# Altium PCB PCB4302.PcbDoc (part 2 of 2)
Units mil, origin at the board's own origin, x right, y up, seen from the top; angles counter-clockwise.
Board outline 1574.8 x 1476.38 mil, 4 copper layers (Top, Inner Layer 2, Inner Layer 3, Bottom), stack 35.4 mil thick; 37 components, 68 nets, 208 pads, 290 vias.
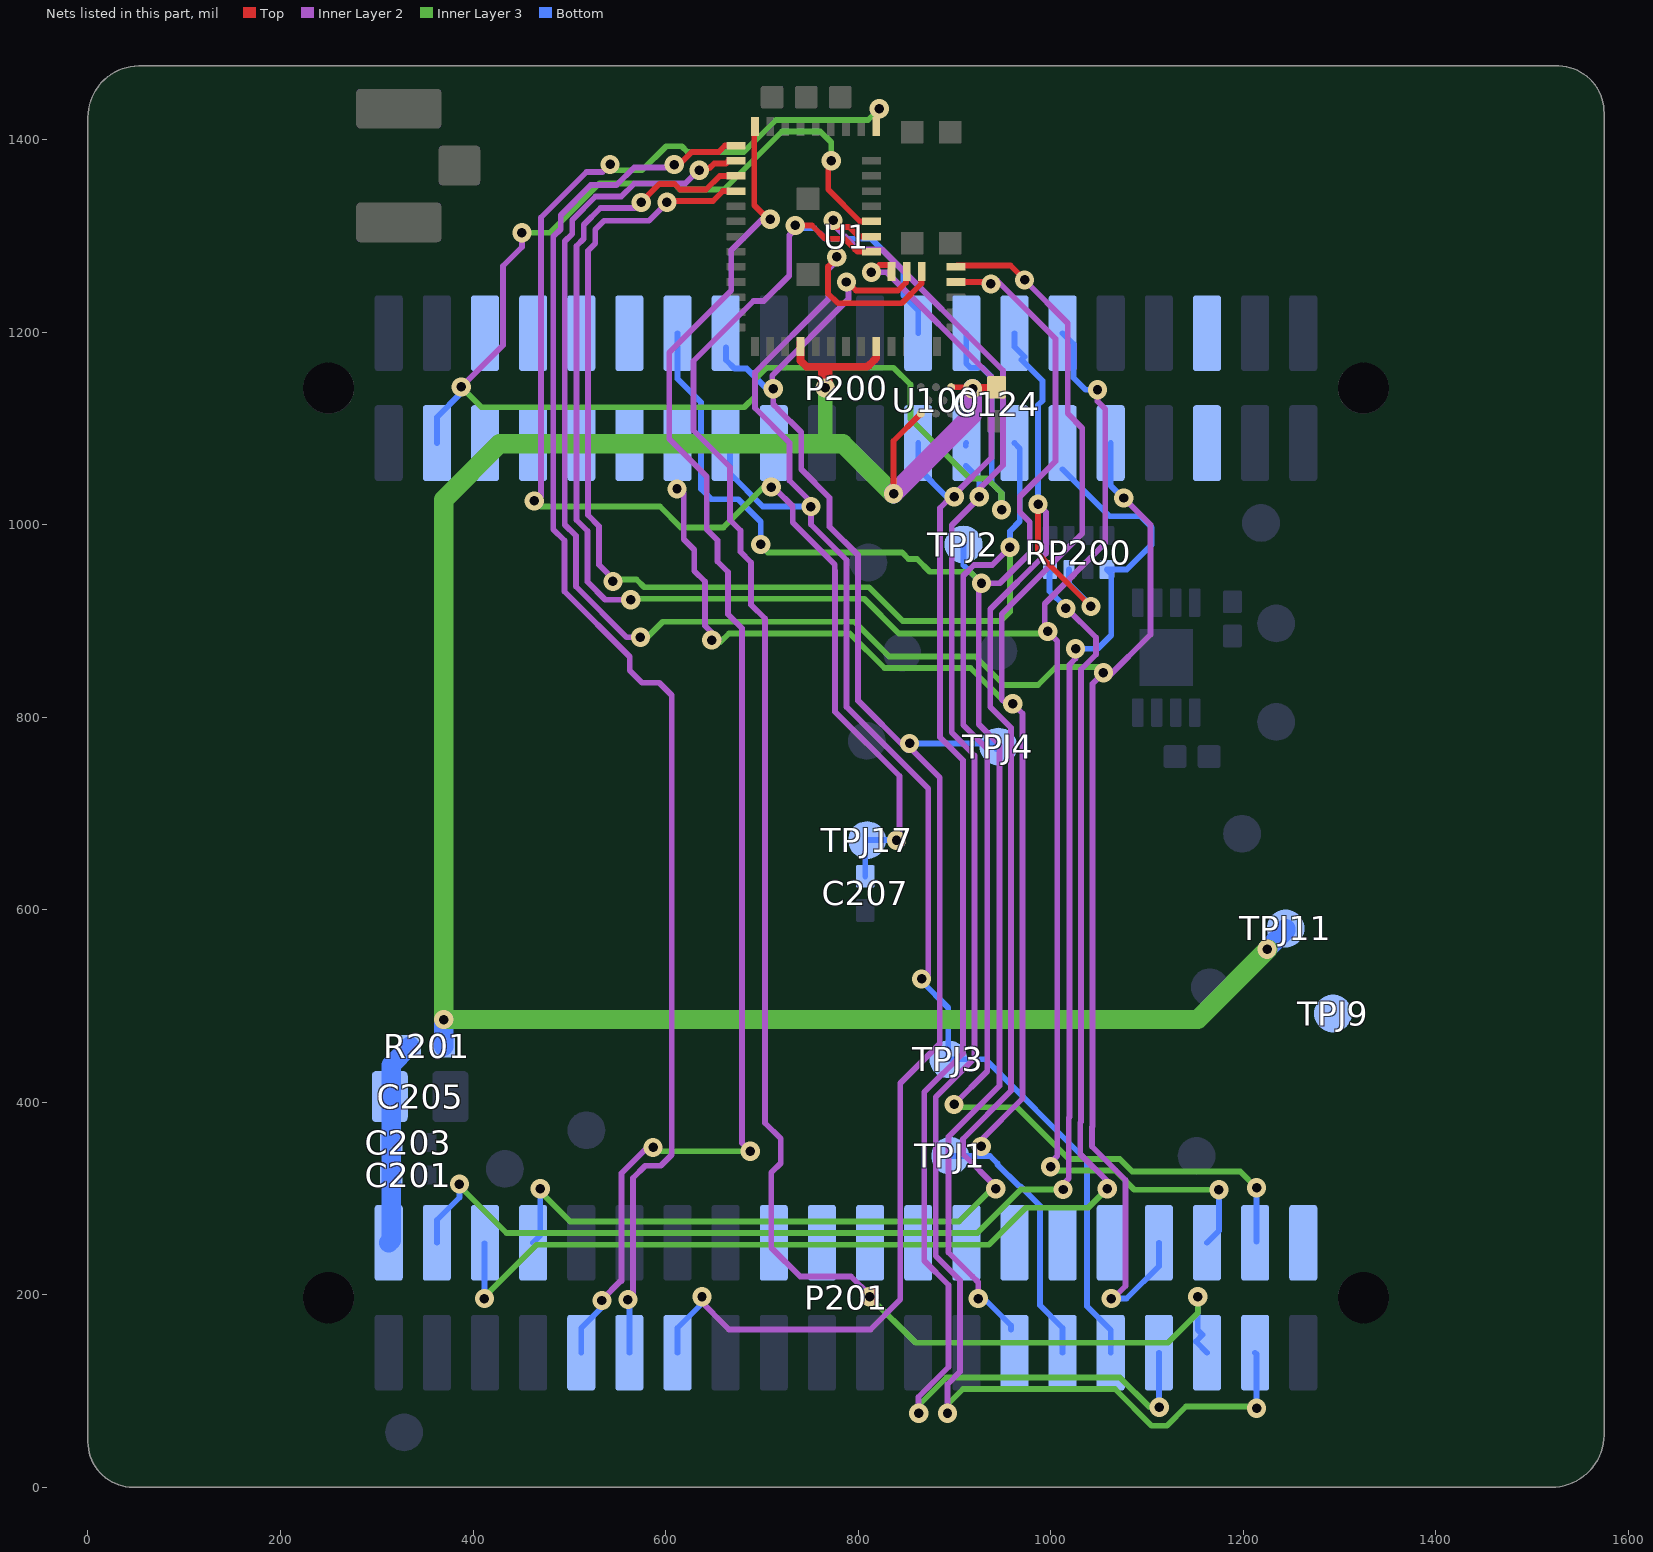
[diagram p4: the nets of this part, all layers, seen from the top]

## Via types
v1: diameter 20, hole 9.84, Top to Bottom, tented both sides, 290 vias

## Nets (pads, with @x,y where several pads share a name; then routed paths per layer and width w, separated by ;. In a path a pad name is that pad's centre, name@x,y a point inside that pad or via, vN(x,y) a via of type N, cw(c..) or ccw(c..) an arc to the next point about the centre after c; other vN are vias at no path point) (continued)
RADIO_PD11: P201.9 U1.9 | length 1515.5
  Top w6: U1.9@692.91,1420 U1.9@692.91,1413.39 692.07,1412.54 692.07,1370.29 692.07,1369.87 692.07,1331.64 v1@707.57,1316.14
  Inner Layer 2 w6: v1(533.85,194) 533.85,194.87 552.98,214 553.85,214 554.13,214.28 554.13,326.12 581.01,353 v1(587,353) ; v1(688,349) 679.32,357.68 679.32,368.43 679.28,368.47 679.28,892.41 664.85,906.84 664.85,950.75 653.85,961.75 653.85,983.81 642.85,994.81 642.85,1049.84 603.85,1088.84 603.85,1178.89 668.2,1243.24 668.2,1284.99 v1@700.41,1317.2 ; v1@700.42,1317.19 v1(708.63,1317.19) 708.63,1316.03 v1@709.8,1317.2
  Inner Layer 3 w6: v1(587,353) 591,349 v1(688,349)
  Bottom w6: P201.9@512.4,139.76 512.4,165.55 533.85,187 v1(533.85,194)
RADIO_PD12: P201.11 U1.10 | length 1487.9
  Top w6: v1@607.92,1375 615.13,1375 627.27,1387.14 655.14,1387.14 661.7,1393.7 U1.10@673.23,1393.7
  Inner Layer 2 w6: v1(560.85,195) 566.13,200.28 566.13,321.15 578.98,334 594.87,334 606.3,345.43 606.3,822.83 593.5,835.63 575.55,835.63 562.71,848.47 562.71,862.76 494.85,930.62 494.85,983.44 483.35,994.94 483.35,1299.26 490.99,1306.91 490.99,1321.43 522.3,1352.74 549.06,1352.74 567.38,1371.06 606.06,1371.06 v1(609,1374)
  Bottom w6: v1(560.85,195) 562.4,193.45 P201.11@562.4,139.76
RADIO_PD13: P200.31 P201.34 U1.11 | length 2238.3
  Top w6: 645.43,1370.08 650.49,1375.14 662.64,1375.14 665.45,1377.95 U1.11@673.23,1377.95
  Inner Layer 2 w6: v1(573.85,883) 559.44,883 506.85,935.59 506.85,988.41 495.35,999.91 495.35,1294.29 502.99,1301.94 502.99,1316.46 527.27,1340.74 554.03,1340.74 567.62,1354.33 620.43,1354.33 633.92,1367.82 v1@635.13,1367.82 ; v1(1062.85,196) 1063.85,195 1077.85,209 1077.85,319.09 1042.85,354.09 1042.85,374.02 1043.46,374.62 1043.46,834.61 v1(1054.85,846) 1059.31,841.54 1103.57,885.8 1103.57,999.86 v1(1075.83,1027.61)
  Inner Layer 3 w6: v1(573.85,883) 580.98,883 596.98,899 796.36,899 832.36,863 921.82,863 951.42,833.4 986.95,833.4 1005.54,852 1049.85,852 1054.85,847 v1(1054.85,846)
  Bottom w6: P200.31@1062.4,1084.65 1062.4,1040.45 1075.24,1027.61 v1(1075.83,1027.61) ; v1(1062.85,196) 1078.85,196 1112.4,229.55 P201.34@1112.4,253.94
  other v1: 635,1368
RADIO_PD14: P200.30 P201.36 U1.12 | length 2228.1
  Top w6: v1(574.8,1334.65) 574.8,1334.99 593.53,1353.71 609.27,1353.71 614.96,1348.02 642.08,1348.02 656.26,1362.2 U1.12@672.24,1362.2
  Inner Layer 2 w6: v1(563.85,922) 537.42,921.99 518.85,940.56 518.85,993.38 507.35,1004.88 507.35,1289.32 514.99,1296.96 514.99,1311.49 532.24,1328.74 568.9,1328.74 v1(574.8,1334.65) ; v1(996.85,889) 1006.92,878.94 1006.85,878.87 1006.85,344 999.85,337 v1(999.85,333) ; v1@997.85,889 993.85,893 993.85,917.81 1056.82,980.78 1056.82,1120.03 1048.67,1128.18 v1(1048.67,1140.02)
  Inner Layer 3 w6: v1@571.88,923 806.3,923 842.3,887 996.85,887 v1(996.85,889) ; v1(999.85,333) 1003.85,329 1066.72,329 1086.72,309 v1(1174.85,309)
  Bottom w6: P200.30@1012.4,1198.82 1023.62,1187.6 1023.62,1152.56 1036.17,1140.02 v1(1048.67,1140.02) ; P201.36@1162.4,253.94 1174.85,266.39 v1(1174.85,309)
RADIO_PD15: P200.27 P201.38 U1.13 | length 2188
  Top w6: v1@595.3,1333.94 597.38,1336.02 649.29,1336.02 659.73,1346.46 U1.13@673.23,1346.46
  Inner Layer 2 w6: v1@540.01,949.16 530.85,958.32 530.85,998.35 519.35,1009.85 519.35,1284.35 526.99,1291.99 526.99,1306.52 536.12,1315.65 582.67,1315.65 593.3,1326.28 593.45,1326.28 v1@601.64,1334.46 ; v1(899.64,397.66) 934.06,432.07 934.06,766.82 909.15,791.73 909.15,946.85 920.28,957.98 939.27,957.98 v1(957.71,976.43)
  Inner Layer 3 w6: v1@551.85,943 569.72,943 577.72,935 811.27,935 846.31,899.96 948.19,899.96 957.71,909.49 v1(957.71,976.43) ; v1(899.64,397.66) 902.61,394.68 965.04,394.68 1018.72,341 1071.69,341 1084.69,328 1196.85,328 v1(1213.85,311)
  Bottom w6: v1(957.71,976.43) 957.71,993.15 967.94,1003.38 967.94,1079.1 P200.27@962.4,1084.65 ; P201.38@1213.85,255.39 v1(1213.85,311)
  other v1: 545.29,940.99 601.4,1334.71
RADIO_PF0: P200.14 P201.27 TPJ2.1 U1.39 | length 1836.2
  Top w6: U1.39@901.57,1251.97 v1@937.01,1251.97
  Inner Layer 2 w6: 918.81,218.96 893.85,243.91 893.85,364.12 946.85,417.12 946.85,771 925.2,792.65 925.2,934.57 928.15,937.53 v1(928.15,938.98) 947.14,938.98 978.35,970.19 978.35,1002.75 967.94,1013.15 967.94,1028.89 1004.92,1065.86 1004.92,1192.93 v1@944.85,1253 ; 918.85,219 924.85,213 v1(924.85,196)
  Inner Layer 3 w6: v1@697.83,979.33 706.17,971 845.71,971 852.4,964.32 861.19,964.32 874.5,951 916.13,951 v1(928.15,938.98) v1@922.15,938.98
  Bottom w6: P200.14@612.4,1198.82 612.4,1151.45 636.85,1127 636.85,1037 647.46,1026.39 675.38,1026.39 689.96,1011.81 698.82,1002.95 v1(698.82,979.33) ; TPJ2.1@909.45,979.25 909.45,957.68 v1(928.15,938.98) ; v1(924.85,196) 930.85,196 958.85,168 P201.27@958.85,164
  other v1: 937.99,1250
RADIO_PF1: P200.13 P201.29 TPJ1.1 U1.40 | length 1855
  Top w6: U1.40@901.57,1267.72 902.86,1269 958.36,1269 v1@973.43,1253.94
  Inner Layer 2 w6: v1(611.85,1037) 614.85,1037 618.85,1033 618.85,984.87 629.85,973.87 629.85,951.81 640.85,940.81 640.85,895 654.85,881 653.85,880 v1(647.85,880) ; v1(927.85,354) 927.85,360.84 970.85,403.84 970.85,803.83 v1(960.67,814.02) ; 950.85,817 949.2,818.65 949.2,907.1 1032.82,990.72 1032.82,1100.19 1017.67,1115.34 1017.67,1209.18 v1@973.85,1253
  Inner Layer 3 w6: v1@656.85,878 665.85,887 791.39,887 827.39,851 916.85,851 953.83,814.02 v1(960.67,814.02)
  Bottom w6: TPJ1.1@895.67,344.21 937.08,344.21 944.85,336.45 944.85,335.13 967.29,312.69 968.6,312.69 988.83,292.46 988.83,189.02 1012.4,165.45 P201.29@1012.4,139.76
  other v1: 972.89,1254.19
RADIO_PF2: P200.15 P201.31 TPJ3.1 U1.41 | length 1641.3
  Top w6: v1@777.85,1277 768.84,1267.99 768.84,1240.02 778.99,1229.87 845.2,1229.87 865.85,1250.52 865.85,1266.29 U1.41@866.14,1266.58
  Inner Layer 2 w6: v1@750.98,1017.72 v1@750.98,1018.75 ; v1(777.85,1278) 777.85,1273.91 768.85,1264.91 768.85,1234 692.85,1158 692.85,1121 728.85,1085 728.85,1045.76 751.01,1023.59 v1(751.01,1018.75) ; v1(865.85,528) 869.85,528 872.85,531 872.85,725.81 788.01,810.66 788.01,963.21 751.01,1000.21 v1(751.01,1018.75)
  Bottom w6: P200.15@666.85,1072 666.85,1053 700.96,1018.89 749.81,1018.89 v1@750,1018.7 ; v1(865.85,528) 865.85,526 893.7,498.15 TPJ3.1@893.7,444.61 932.24,444.61 1037.85,339 1037.85,188 1062.4,163.45 P201.31@1062.4,139.76
RADIO_PF3: P200.16 P201.13 TPJ4.1 U1.42 | length 1738.1
  Top w6: v1@793.31,1253.94 793.98,1253.27 790.85,1250.14 790.85,1250 797.74,1243.11 841.47,1243.11 849.85,1251.49 U1.42@849.85,1260
  Inner Layer 2 w6: v1(637.82,197.84) 635.69,197.84 633.85,196 665.85,164 812.85,164 843.85,195 843.85,419.65 884.85,460.65 884.85,737.2 856.21,765.84 851.29,765.84 800.01,817.12 800.01,968.19 770.37,997.82 770.37,1027.86 740.85,1057.38 740.85,1095.84 716.77,1119.92 ; v1(711.85,1141) 711.85,1125 716.85,1120 ; v1@711.85,1142 710.85,1143 710.85,1155 789.86,1234.01 v1@789.86,1251.13
  Bottom w6: P201.13@612.4,139.76 612.4,165.55 637.82,190.97 v1(637.82,197.84) ; P200.16@662.85,1184 662.85,1171 671.85,1162 684.26,1162 v1@708.26,1138 ; v1(853.38,772.68) 930.38,772.68 934.28,776.57 943.85,767 TPJ4.1@944.85,768
  other v1: 787.85,1252
RADIO_PF4: P200.23 P201.33 U1.43 | length 1767.6
  Top w6: v1@812.17,1260 821.85,1269.69 834.65,1269.69 U1.43@834.65,1262.8 ; v1@813.85,1261.69 v1(813.85,1262.11)
  Inner Layer 2 w6: v1(813.85,1262.11) 829.74,1262.11 938.6,1153.25 938.6,1069.75 v1@899.85,1031 ; v1(862.85,77) 862.85,93.84 893.85,124.84 893.85,209.97 868.61,235.21 868.61,410.46 908.85,450.71 908.85,755.28 885.15,778.98 885.15,1017.3 896.85,1029 v1(899.85,1029)
  Inner Layer 3 w6: v1(862.85,77) 862.85,85 891.85,114 1071.85,114 1102.85,83 v1(1112.85,83)
  Bottom w6: P200.23@862.4,1084.65 862.4,1058.45 892.35,1028.5 892.85,1029 v1(899.85,1029) ; P201.33@1112.4,139.76 1112.4,83.45 v1(1112.85,83)
RADIO_PF5: P200.24 P201.35 U1.44 | length 2029.7
  Top w6: v1(734.63,1310.77) 752.02,1310.77 765.79,1297 785.72,1297 796.85,1285.87 ; 796.85,1285.83 799.21,1283.46 U1.44@813.98,1283.46
  Inner Layer 2 w6: v1(734.63,1310.77) 734.63,1306.8 728.4,1300.58 728.35,1300.63 728.35,1258.6 702.03,1232.28 691.18,1232.28 628.85,1169.95 628.85,1097.78 666.85,1059.78 666.85,1004.75 677.85,993.75 677.85,971.69 688.85,960.69 688.85,916.78 703.28,902.35 703.28,378.41 719.52,362.17 719.52,336.68 709.85,327.01 709.85,248.91 739.76,219 792.72,219 811.85,199.87 v1(811.85,198)
  Inner Layer 3 w6: v1(811.85,198) 859.85,150 1121.85,150 1152.85,181 v1(1152.85,198)
  Bottom w6: v1@734.16,1308.07 754.72,1308.07 765.79,1297 781.87,1297 813.61,1297.01 846.85,1263.77 846.85,1238 862.4,1222.45 P200.24@862.4,1198.82 ; v1(1152.85,198) 1152.85,163.32 1157.85,158.32 1150.85,151.32 P201.35@1162.4,139.76
RADIO_PF6: P200.25 P201.37 U1.45 | length 1908.1
  Top w6: v1@771.65,1312.01 774.66,1309 790.69,1309 800.48,1299.21 U1.45@813.98,1299.21
  Inner Layer 2 w6: v1(774,1316) 773.15,1316 770.89,1313.76 770.89,1314.96 799.85,1286 824.62,1286 950.6,1160.03 950.6,1061.75 924.85,1036 928.85,1032 928.85,1031 897.15,999.3 897.15,783.95 920.85,760.25 920.85,445.74 880.61,405.49 880.61,240.18 905.85,214.94 905.85,119.87 892.85,106.87 v1(892.85,77)
  Inner Layer 3 w6: v1(892.85,77) 892.85,86 908.85,102 1066.88,102 1104.88,64 1120.72,64 1140.72,84 1211.85,84 v1(1213.85,82)
  Bottom w6: P200.25@911.85,1061 925.85,1047 v1(925.85,1029) ; P200.25@911.85,1082 911.85,1084.09 P200.25@912.4,1084.65 ; P201.37@1212.4,139.76 1213.85,138.32 v1(1213.85,82)
RADIO_PF7: P200.3 P200.26 U1.46 | length 1634
  Top w6: v1@769.23,1377.3 768.98,1377.06 768.98,1347.97 801.99,1314.96 U1.46@813.98,1314.96 U1.46@814.96,1314.96
  Inner Layer 2 w6: v1(387.85,1143) 431.1,1186.25 431.1,1268.7 450.79,1288.39 v1(450.79,1303.15)
  Inner Layer 3 w6: v1(387.85,1143) 408.85,1122 681.72,1122 692.85,1133.13 692.85,1151 704.85,1163 836.72,1163 854.29,1145.44 854.29,1109.56 915.85,1048 933.72,1048 944.72,1037 944.85,1037 948.95,1032.91 v1(948.95,1015.33) ; v1(450.79,1303.15) 480.03,1303.15 531.21,1354.33 608.65,1354.33 609.27,1353.71 ; 608.58,1353.71 609.27,1353.71 ; v1(772,1378) 772,1397.17 760.77,1408.41 720.94,1408.41 660.72,1348.19 614.79,1348.19 609.27,1353.71
  Bottom w6: P200.3@362.4,1084.65 362.4,1111.55 387.85,1137 v1(387.85,1143) ; P200.26@912.4,1198.82 912.4,1167.45 916.85,1163 928.85,1163 938.83,1153.02 938.83,1043.24 948.95,1033.13 v1(948.95,1015.33)
USB_VBUS: P200.35
USB_VREG: P200.36
VMCU: C124.1 R201.2 TPJ11.1 U1.26 U1.31 U100.A1 U100.E3 | length 2476.3
  Top w6: v1(836.85,1032) 836.85,1086.97 U100.E3@865.1,1115.22 ; U100.A1@896.6,1142.78 v1@917.07,1142.78
  Top w8: U1.26@740.16,1188.83 740.16,1170.28 746.43,1164 809.6,1164 810.79,1165.2 811.23,1165.2 817.09,1171.05 817.09,1171.49 818.6,1173 818.9,1173 U1.31@818.9,1185.04
  Top w10: v1(918.85,1141) C124.1@946.13,1141
  Top w15: v1(765.85,1142) 765.85,1160
  Inner Layer 2 w20: v1(836.85,1032) 918.85,1114 v1(918.85,1141)
  Inner Layer 3 w15: 765.85,1084 v1(765.85,1142) v1@765.85,1143
  Inner Layer 3 w20: v1(836.85,1032) 836.11,1032 784.11,1084 765.85,1084 427.5,1084 369.68,1026.18 v1(369.68,485.83) 1152.68,485.83 1225.85,559 v1(1224.85,559)
  Bottom w20: R201.2@369.68,457.99 v1(369.68,485.83) ; v1(1224.85,559) 1244.09,578.24 TPJ11.1@1244.09,580.43
VMCU_IN: C201.1 C203.1 C205.1 P201.2 R201.1 | length 213.1
  Bottom w20: P201.2@312.4,253.94 314.96,256.49 C201.1@314.96,324.14 C203.1@314.96,357.99 314.96,438.7 R201.1@334.25,457.99
VRF: TPJ9.1
VRF_IN: P201.40
WSTK_F4: C207.1 P200.17 TPJ17.1 U1.1 | length 1479.8
  Inner Layer 2 w6: v1@463.58,1022.64 470.47,1029.53 470.47,1318.9 517.72,1366.14 534.4,1366.14 v1(542.34,1374.08) ; v1(709.85,1039) 707.38,1036.53 714.46,1036.53 732.01,1018.97 732.01,1002.24 775.78,958.47 775.78,952.57 776.01,952.34 776.01,805.69 842.85,738.84 v1@842.85,673
  Inner Layer 3 w6: v1(463.58,1024.61) 463.58,1022.64 465.06,1024.11 470.47,1018.7 594.15,1018.7 615.85,997 660.01,997 702.01,1039 v1(709.85,1039) ; v1@541.34,1374.02 547.35,1368 575.61,1368 600.62,1393.02 616.85,1393.02 622.85,1387.02 681.25,1387.02 714.64,1420.41 810.26,1420.41 v1(821.85,1432)
  Bottom w6: C207.1@807.4,634.57 807.4,670.28 TPJ17.1@809.35,672.23 v1@837.62,672.23
  other v1: 839.85,672
WSTK_F15: P200.28 P201.8 RP200.7 | length 1723
  Top w6: v1(986.94,1021.02) 986.94,969.91 v1(1041.85,915)
  Inner Layer 2 w6: v1(942.85,310) 942.85,312.13 908.85,346.13 908.85,361.87 958.85,411.87 958.85,788.96 937.2,810.62 937.2,912.07 995.08,969.95 995.08,1012.88 v1(986.94,1021.02)
  Inner Layer 3 w6: v1(469.85,310) 466.85,310 500.85,276 904.85,276 941.85,313 942.85,312 v1(942.85,310)
  Bottom w6: P201.8@462.4,253.94 469.85,261.39 v1(469.85,310) ; P200.28@962.4,1198.82 962.4,1184.82 972.85,1174.37 969.61,1171.13 991.44,1149.31 991.44,1128.64 986.94,1124.15 v1(986.94,1021.02) ; RP200.7@1019.01,953.28 1019.01,938.84 1041.85,916 v1(1041.85,915)
WSTK_F16: P200.29 P201.4 RP200.5 | length 1613.8
  Inner Layer 2 w6: v1(1012.93,309.31) 1012.93,311.22 1011.15,313 1018.85,320.7 1018.85,383.96 1019.46,384.56 1019.46,854.51 1025.85,860.9 v1(1025.85,871)
  Inner Layer 3 w6: v1(385.85,315) 384.85,314 434.85,264 923.72,264 969.03,309.31 v1(1012.93,309.31)
  Bottom w6: P201.4@362.4,253.94 362.4,277.55 385.85,301 v1(385.85,315) ; P200.29@1012.4,1057.45 1061.24,1008.61 1093.24,1008.61 1104.85,997 1104.85,979 1079.13,953.28 RP200.5@1058.38,953.28 1062.85,948.81 1062.85,885 1048.85,871 v1(1025.85,871)
WSTK_P3: P201.6 RP200.8 | length 1434.1
  Inner Layer 2 w6: v1(1015.85,912.94) 1016.75,912.94 1046.98,882.71 1046.98,865 1031.46,849.48 1031.46,379.59 1030.85,378.99 1030.85,346 1058.85,318 v1(1058.85,310)
  Inner Layer 3 w6: v1(411.85,196) 411.85,198 465.85,252 935.85,252 974.16,290.31 1039.16,290.31 v1(1058.85,310)
  Bottom w6: v1(411.85,196) P201.6@411.85,253.39 ; RP200.8@1000.86,951.75 998.84,949.74 998.84,930.85 1015.85,913.84 v1(1015.85,912.94)
WSTK_P15: P201.18
WSTK_P17: P201.20
WSTK_P19: P201.22
WSTK_P21: P201.24
WSTK_P23: P201.26
WSTK_P25: P201.28
WSTK_P27: P201.30
WSTK_P29: P201.32
WSTK_P38: P200.5
WSTK_P39: P200.6
WSTK_P40: P200.7
WSTK_P41: P200.8
WSTK_P42: P200.9
WSTK_P43: P200.10
WSTK_P44: P200.11
WSTK_P45: P200.12
pads on no net: P200.M1 P200.M2 P201.M1 P201.M2 RP200.3 RP200.6 TPJ18.1 TPJ19.1 TPJ20.1 U1.28 U1.30 U100.C1 U200.9

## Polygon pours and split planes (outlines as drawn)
GND on Top "GND_TOP" (solid, pour order 8): 21.82,64.94 ccw(c66.5,64.94) 66.5,20.27 1528.11,20.27 ccw(c1526.17,48.94) 1554.85,50.88 1555.12,1419.29 844.46,1419.22 844.46,1454.94 56.82,1454.94 ccw(c56.82,1419.95) 21.82,1419.94
GND on Inner Layer 3 "GND_L3" (solid, pour order 7): 21.82,64.94 ccw(c66.5,64.94) 66.5,20.27 1528.11,20.27 ccw(c1526.17,48.94) 1554.85,50.88 1555.12,1419.29 844.46,1419.22 844.46,1454.94 56.82,1454.94 ccw(c56.82,1419.95) 21.82,1419.94
GND on Inner Layer 2 "GND_L2" (solid, pour order 6): 21.82,64.94 ccw(c66.5,64.94) 66.5,20.27 1528.11,20.27 ccw(c1526.17,48.94) 1554.85,50.88 1555.12,1419.29 844.46,1419.22 844.46,1454.94 56.82,1454.94 ccw(c56.82,1419.95) 21.82,1419.94
GND on Bottom "GND_Bottom" (solid, pour order 5): 21.82,64.94 ccw(c66.5,64.94) 66.5,20.27 1528.11,20.27 ccw(c1526.17,48.94) 1554.85,50.88 1555.12,1419.29 844.46,1419.22 844.46,1454.94 56.82,1454.94 ccw(c56.82,1419.95) 21.82,1419.94

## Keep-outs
Keep-Out Layer:
  lines w1: 0,54 0,1426.18 ; 0,54.05 ccw(c52.94,52.94) 53.96,0 ; 0.07,1425.2 cw(c51.46,1425.09) 48.23,1476.38 1527.56,1476.38 cw(c1522.33,1424.01) 1574.76,1419.42 ; 149.61,0 1330.85,0 ; 1527.67,-0.01 ccw(c1518.81,55.29) 1574.8,56.17 ; 1574.8,56.23 1574.8,1426.18

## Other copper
Top:
  region: 352.85,759
  region: 303.85,799
  pour cut-out: 780.85,1418 780.85,1407 810.85,1407 810.85,1418
  pour cut-out: 807.85,1427 807.85,1282 829.85,1282 829.85,1427
Inner Layer 2:
  pour cut-out: 277,1411 362,1411 362,1399 413,1399 413,1347 362,1347 362,1335 277,1335
Bottom:
  pour cut-out: 339.85,394.73 333.85,394.73 333.85,414.73 339.85,414.73 339.85,394.73

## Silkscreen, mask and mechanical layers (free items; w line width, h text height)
Solder Mask Top:
  lines w39.37: 0,52.13 ccw(c53.33,53.06) 52.4,-0.27 ; 0,53.06 0,1421.26 ; 0.14,1425.33 cw(c51.54,1424.98) 51.18,1476.38 ; 47.24,0 1515.75,0 ; 57.15,1476.07 1527.62,1476.1 ; 1521.18,-0.27 ccw(c1520.81,53.62) 1574.7,53.24 ; 1524.54,1476.44 cw(c1523.65,1425.29) 1574.8,1426.18 ; 1574.8,53.62 1574.8,1429.13
Solder Mask Bottom:
  lines w39.37: 0,53.32 0,1420.28 ; 0.14,1425.34 cw(c51.54,1424.98) 51.18,1476.38 ; 0.39,52.39 ccw(c53.71,53.32) 52.78,0 ; 54.13,1476.38 1524.61,1476.45 ; 55.12,0 1515.75,0 ; 1521.57,-0.01 ccw(c1521.19,53.88) 1575.08,53.51 ; 1524.54,1476.44 cw(c1523.65,1425.29) 1574.8,1426.18 1574.8,53.88
Board_Outline:
  lines w2.99: 0,47.18 ccw(c46.96,46.96) 46.75,0 ; 0,1423.11 cw(c53,1423.38) 52.74,1476.38 ; 1520.21,0 ccw(c1520.4,54.4) 1574.8,54.22 ; 1527.85,1476.38 cw(c1526.72,1428.3) 1574.8,1427.17
  lines w3: -0.15,47.88 -0.85,56.08 -2.95,63.98 -6.45,71.38 -11.15,78.08 -16.85,83.78 -23.55,88.48 -30.95,91.98 -38.85,94.08 -46.95,94.78 -47.75,94.78 -55.95,94.08 -63.85,91.98 -71.25,88.48 -77.85,83.78 -83.65,78.08 -88.35,71.38 -91.85,63.98 -93.95,56.08 -94.65,47.88 -94.65,39.68 -92.65,16.38 -86.55,-6.12 -76.75,-27.32 -63.35,-46.42 -46.85,-62.92 -27.75,-76.32 -6.55,-86.12 15.95,-92.22 39.25,-94.22 1535.25,-94.22 1558.55,-92.22 1581.05,-86.12 1602.25,-76.32 1621.35,-62.92 1637.85,-46.42 1651.25,-27.32 1661.05,-6.12 1667.15,16.38 1669.15,39.68 1669.15,47.88 1668.45,56.08 1666.35,63.98 1662.85,71.38 1658.15,78.08 1652.45,83.78 1645.75,88.48 1638.35,91.98 1630.45,94.08 1622.25,94.78 1621.55,94.78 1613.35,94.08 1605.45,91.98 1598.05,88.48 1591.35,83.78 1585.65,78.08 1580.95,71.38 1577.45,63.98 1575.35,56.08 ; -0.15,1429 -0.85,1420.9 -2.95,1413 -6.45,1405.6 -11.05,1398.9 -16.85,1393.1 -23.55,1388.4 -30.95,1385 -38.85,1382.9 -46.95,1382.2 -47.75,1382.2 -55.95,1382.9 -63.85,1385 -71.25,1388.4 -77.85,1393.1 -83.65,1398.9 -88.35,1405.6 -91.85,1413 -93.95,1420.9 -94.65,1429 -94.65,1437.3 -92.65,1460.5 -86.55,1483.1 -76.75,1504.2 -63.35,1523.3 -46.85,1539.8 -27.75,1553.2 -6.55,1563.1 15.95,1569.1 39.25,1571.1 1535.25,1571.1 1558.55,1569.1 1581.05,1563.1 1602.25,1553.2 1621.35,1539.8 1637.85,1523.3 1651.25,1504.2 1661.05,1483.1 1667.15,1460.5 1669.15,1437.3 1669.15,1429 1668.45,1420.9 1666.35,1413 1662.85,1405.6 1658.15,1398.9 1652.45,1393.1 1645.75,1388.4 1638.35,1385 1630.45,1382.9 1622.25,1382.2 1621.55,1382.2 1613.35,1382.9 1605.45,1385 1598.05,1388.4 1591.45,1393.1 1585.65,1398.9 1580.95,1405.6 1577.45,1413 1575.35,1420.9 ; 0,47.18 0,1423.11 ; 46.75,0 1520.21,0 ; 52.74,1476.38 1527.85,1476.38 ; 1574.8,54.22 1574.8,1427.17
Variant_A_Top_Silk:
  drawing of 24289 lines, arcs and shapes, not listed
  text "BGM121" at 639.85,86 h80
Variant_A_Bottom_Silk:
  text "PCB4302A Rev A03" at 1507.87,992.13 h80 r90
Variant_B_Top_Silk:
  text "_____ Gecko" at 185.85,723 h200
Drill Drawing:
  lines w1: 102.42,-0.27 102.45,-0.27
Bottom_Silk:
  lines w6: 250.25,1284.26 250.25,1244.86 289.55,1244.86 ; 250.25,1426.89 250.25,1466.29 289.55,1466.29 ; 958.85,1245.08 998.03,1245.08 998.03,1285.43 ; 958.85,1461.37 998.25,1461.37 998.25,1421.97
  text "BOARD" at 1055.12,1447.83 h60 r90
  text "INFO" at 1105.31,1413.39 h60 r90
Mechanical 26:
  lines w7.87: -4779.72,-1652.05 -4582.87,-1652.05 ; -4779.72,198.35 -4582.87,198.35 ; -4779.24,2048.74 -4582.87,2048.74 ; -1976.27,-3503.68 -1976.27,-3306.83 ; -1976.27,3779.79 -1976.27,3976.64 ; 830.81,-3503.68 830.81,-3306.83 ; 830.81,3779.79 830.81,3976.64 ; 3633.96,-3503.68 3633.96,-3306.83 ; 3633.96,3779.79 3633.96,3976.64 ; 6243.91,-1652.05 6440.76,-1652.05 ; 6243.91,198.35 6440.76,198.35 ; 6243.91,2048.74 6440.28,2048.74 ; -4779.24,-3503.68 -4779.24,3976.32 6440.76,3976.32 6440.76,-3503.68 -4779.24,-3503.68 ; -4582.87,-3306.83 -4582.87,3779.79 6243.91,3779.79 6243.91,-3306.83 -4582.87,-3306.83
  text "1" at -3484.43,3841.66 h60
  text "2" at -637.69,3841.66 h60
  text "3" at 2220.58,3841.66 h60
  text "4" at 5007.98,3841.66 h60
  text "D" at 6322.57,3088.11 h60
  text "D" at -4705.43,3040.66 h60
  text "C" at -4705.43,1170.79 h60
  text "C" at 6317.57,1170.79 h60
  text "B" at -4705.43,-703.23 h60
  text "B" at 6317.57,-703.23 h60
  text "A" at -4705.43,-2573.31 h60
  text "A" at 6317.57,-2573.31 h60
  text "1" at -3436.43,-3442.34 h60
  text "2" at -637.69,-3442.34 h60
  text "3" at 2208.76,-3442.34 h60
  text "4" at 4992.23,-3442.34 h60
Mechanical 27:
  circle w6: c2937.31,-2462.15 r30
  circle w6: c2937.31,-2462.15 r70
  circle w10: c1678.07,-3031.3 r116.62
  lines w6: 2504.31,-2462.15 2794.31,-2462.15 ; 2847.31,-2462.15 3027.31,-2462.15 ; 2534.31,-2492.15 2763.31,-2532.15 2764.31,-2392.15 2534.31,-2432.15 2534.31,-2492.15
  lines w7.87: 1518.69,-3304.3 1518.69,-2246.83 3094.04,-2246.83 ; 1518.69,-2744.3 6241.69,-2744.3 ; 1519.24,-2601.16 3094.04,-2601.16 ; 2317.69,-3302.3 2317.69,-2747.3 ; 2317.69,-2599.3 2317.69,-2248.3 ; 5456.24,-2743.3 5456.24,-2601.16 ; 5798.95,-2601.16 5798.95,-2246.83 ; 6243.65,-2601.16 3094.04,-2601.16 ; 6243.65,-2246.83 3094.04,-2246.83 ; 3094.04,-2601.16 3094.04,-2246.83
  text "SIZE" at 1597.98,-2325.57 h60
  text "DOC NO" at 3172.78,-2325.57 h60
  text "REV" at 5828.85,-2333 h60
  text "PROJECTION" at 2357.69,-2339.3 h60
  text "A03" at 5833.85,-2519 h100
  text "A4" at 1702.31,-2537.15 h100
  text "PCB4302" at 3271.19,-2537.15 h100
  text "REF" at 1597.98,-2679.9 h60
  text "SHEET" at 5495.62,-2679.9 h60
  text "1 of 2" at 5883.08,-2720.72 h60
  text "This drawing is confidential and is supplied on the express" at 2336.69,-2861.3 h60
  text "condition that it shall not be loaned, copied or disclosed to any" at 2336.69,-2961.3 h60
  text "other person or used for any purpose without the written consent of" at 2336.69,-3061.3 h60
  text "C" at 1654.69,-3071.3 h80
  text "2016" at 1854.69,-3077.3 h100
  text "SILICON LABS" at 2353.69,-3230.3 h100
Mechanical 28:
  lines w7.87: -4776.72,-1655.05 -4579.87,-1655.05 ; -4776.72,195.35 -4579.87,195.35 ; -4776.24,2045.74 -4579.87,2045.74 ; 6246.91,-1655.05 6443.76,-1655.05 ; 6246.91,2045.74 6443.76,2045.74
  lines w8: -4580.87,-3309.83 -4580.87,3776.79 ; -4579.87,-3309.83 6246.91,-3309.83 6246.91,3776.79 -4579.87,3776.79 ; -1973.27,-3506.68 -1973.27,-3309.83 ; -1973.27,3776.79 -1973.27,3973.64 ; 833.81,-3506.68 833.81,-3309.83 ; 833.81,3776.79 833.81,3973.64 ; 3636.96,-3506.68 3636.96,-3309.83 ; 3636.96,3776.79 3636.96,3973.64 ; -4776.24,-3506.68 6443.76,-3506.68 6443.76,3973.32 -4776.24,3973.32 -4776.24,-3506.68
  text "4" at -3441.43,3838.66 h60
  text "3" at -594.69,3838.66 h60
  text "2" at 2263.58,3838.66 h60
  text "1" at 5050.98,3838.66 h60
  text "D" at 6365.57,3085.11 h60
  text "D" at -4662.43,3037.66 h60
  text "C" at -4662.43,1167.79 h60
  text "C" at 6365.57,1104.8 h60
  text "B" at -4662.43,-706.23 h60
  text "B" at 6365.57,-749.54 h60
  text "A" at 6325.47,-2573.31 h60
  text "A" at -4662.43,-2576.31 h60
  text "A" at 6360.57,-2576.31 h60
  text "4" at -3393.43,-3445.34 h60
  text "3" at -594.69,-3445.34 h60
  text "2" at 2245.76,-3445.34 h60
  text "1" at 5035.23,-3445.34 h60
Mechanical 29:
  circle w6: c-1269.72,-2464.68 r30
  circle w6: c-1269.72,-2464.68 r70
  circle w10: c-10.47,-3033.83 r116.62
  lines w6: -1359.72,-2464.68 -1179.72,-2464.68 ; -1126.72,-2464.68 -836.72,-2464.68 ; -1096.72,-2394.68 -1095.72,-2534.68 -866.72,-2494.68 -866.72,-2434.68 -1096.72,-2394.68
  lines w7.87: -4576.05,-2603.69 -1426.45,-2603.69 ; -4576.05,-2249.35 -1426.45,-2249.35 ; -4574.09,-2746.83 148.91,-2746.83 ; -4117.35,-2603.69 -4117.35,-2249.35 ; -3788.65,-2745.83 -3788.65,-2603.69 ; -650.09,-3304.83 -650.09,-2749.83 ; -650.09,-2601.83 -650.09,-2250.83 ; 148.36,-2603.69 -1426.45,-2603.69 ; 148.36,-2249.35 -1426.45,-2249.35 ; 148.91,-3306.83 148.91,-2246.83 ; -1426.45,-2603.69 -1426.45,-2249.35
  text "DOC NO" at -1505.19,-2328.09 h60
  text "SIZE" at 69.61,-2328.09 h60
  text "REV" at -4157.15,-2331 h60
  text "PROJECTION" at -690.09,-2341.83 h60
  text "A03" at -4159.15,-2521 h100
  text "PCB4302" at -1603.6,-2539.68 h100
  text "A4" at -34.72,-2539.68 h100
  text "SHEET" at -3828.02,-2682.43 h60
  text "REF" at 69.61,-2682.43 h60
  text "2 of 2" at -4209.44,-2720.72 h60
  text "This drawing is confidential and is supplied on the express" at -669.09,-2863.83 h60
  text "condition that it shall not be loaned, copied or disclosed to any" at -669.09,-2963.83 h60
  text "other person or used for any purpose without the written consent of" at -669.09,-3063.83 h60
  text "C" at 12.91,-3073.83 h80
  text "2016" at -187.09,-3079.83 h100
  text "SILICON LABS" at -686.09,-3232.83 h100
Mechanical 30:
  lines w7.87: 1518.69,-2246.83 1518.69,-1426.36 6243.1,-1426.36 ; 1518.69,-2091.87 3093.49,-2091.87 ; 1518.69,-1934.39 3093.49,-1934.39 ; 1518.69,-1776.91 3093.49,-1776.91 ; 3093.49,-1934.43 6243.1,-1934.43 ; 3093.49,-1619.43 6243.1,-1619.43 ; 3093.76,-2246.83 3093.76,-1426.36 ; 3093.76,-1425.96 3093.76,-1141.09 6245.06,-1141.09
  text "CUSTOMER" at 3137.13,-1501.83 h50
  text "PROJECT NO" at 1577.13,-1541.83 h60
  text "SILICON LABS" at 3823.82,-1574.8 h98.43
  text "DRAWING TITLE" at 3146.13,-1695.83 h60
  text "BRD4302" at 1627.13,-1716.83 h130
  text "DATE" at 1577.13,-1861.83 h60
  text "BGM121 Radio Board" at 3142.72,-1863.19 h70.87
  text "2016-09-05" at 2297.13,-1901.83 h60
  text "SHEET NAME" at 3138.13,-2016.83 h60
  text "DRAWN" at 1577.13,-2021.83 h60
  text "CHECK" at 1577.13,-2181.83 h60

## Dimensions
149.61,0 to -41.34,1476.38 on Assembly Drawing Top
0,1421.26 to 1574.8,1429.13 on Assembly Drawing Top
